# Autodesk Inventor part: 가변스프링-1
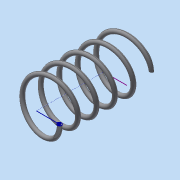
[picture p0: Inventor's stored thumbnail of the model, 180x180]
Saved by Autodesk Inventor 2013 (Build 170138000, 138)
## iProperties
Created: 2020-07
Part Number: 가변스프링-1
Material: 스테인리스강
Document SubType Name: Modeling
Designer: dgall
Density: 8.08 g/cm^3
Mass: 8.65612 g
Surface Area: 21.682 cm^2
Volume: 1.0713 cm^3
Author: dgall
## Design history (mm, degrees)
sketch "스케치1"
  geometry: L1 (11, 0)-(0, 0); L2 (0, 0)-(0, 32.11); L3 (0, 32.11)-(11, 32.11); C1 r 1 at (11, 0)
  constraints: 6 end point, 2 horizontal, 1 centre point, 1 coincident, 1 perpendicular, 1 vertical alignment
  dimensions: "d0" = 2 diameter of C1; "d2" = 32.11 dimension on L1.end L2.end (derived); "d3" = 11 distance of L2.end L3.end
feature "코일1" pitch "d4" = 10; turns "d6" = 5; dims "d5" = 32.11 (= d2), "d7" = 0, angle "d8" = 90 deg, angle "d9" = 90 deg, "d10" = 0, "d11" = 0
node "작업 평면2"
  node "작업 평면1"
feature "분할1"
feature "분할2"
node "솔리드1"
other parameters: "d12" = 0, "d13" = 0
